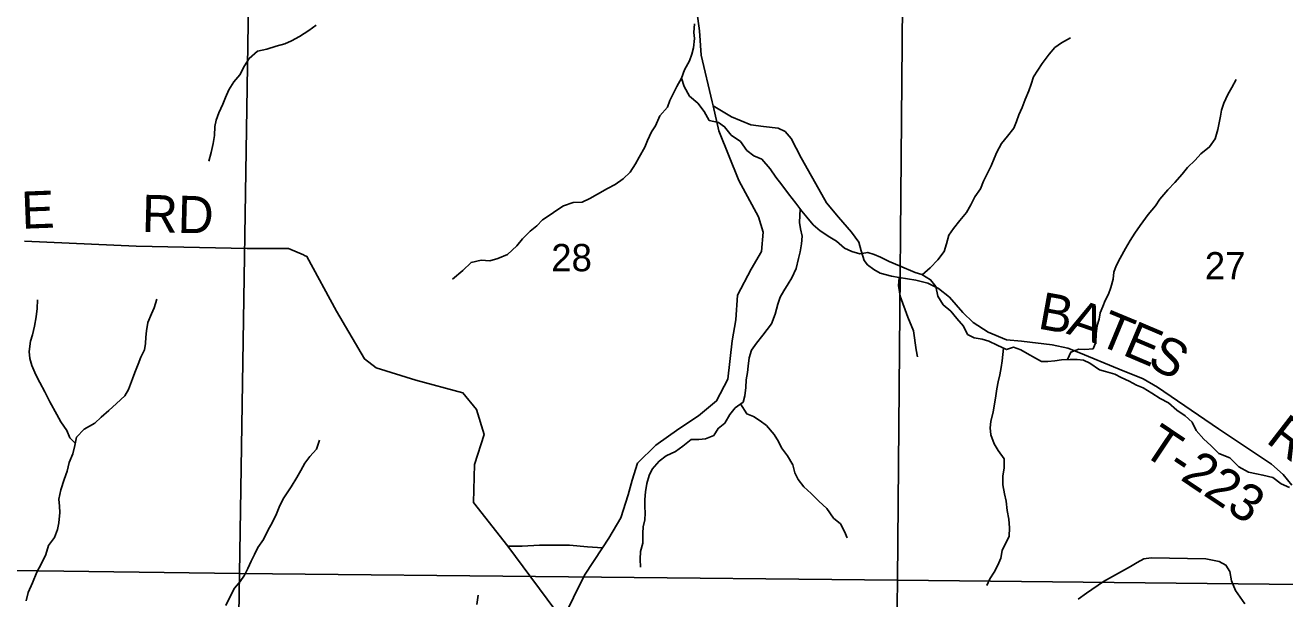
# Model space of a CAD drawing. Extents: x 2043100 to 2470832, y 443715 to 810583.
# Drawn here: x 2268319 to 2278495, y 675442 to 680076 of the extents above; entities that cross this region are included whole.
import ezdxf

# ---------------------------------------------------------------- set-up
doc = ezdxf.new("R2010")
doc.units = 0
for name, color, linetype in [('GM_X_County_Road', 7, 'Continuous'), ('GM_X_County_Road_Text', 7, 'Continuous'), ('GM_X_Minor_River', 7, 'Continuous'), ('GM_X_Section', 7, 'Continuous'), ('GM_X_Section_Text', 7, 'Continuous'), ('GM_X_State_Route', 7, 'Continuous'), ('GM_X_Township_Road', 7, 'Continuous'), ('GM_X_Township_Road_Text', 7, 'Continuous')]:
    doc.layers.add(name, color=color, linetype=linetype)

msp = doc.modelspace()

# ---------------------------------------------------------------- linework, layer by layer
at = {"layer": 'GM_X_County_Road'}
for points in [[(2268313, 678330), (2269216, 678290), (2270112, 678271), (2270447, 678271), (2270567, 678220)], [(2270567, 678220), (2270577, 678216), (2270595, 678208), (2270833, 677765), (2271060, 677380), (2271155, 677307), (2271474, 677209), (2271855, 677107), (2271966, 676970), (2272026, 676770), (2271949, 676527), (2271942, 676220), (2272218, 675867), (2272660, 675271)], [(2276826, 675440), (2276893, 675488), (2277031, 675582), (2277249, 675703), (2277302, 675734), (2277357, 675764), (2277415, 675773), (2277856, 675765), (2277966, 675744), (2278020, 675714), (2278051, 675662), (2278065, 675587), (2278097, 675510), (2278173, 675401)]]:
    msp.add_lwpolyline(points, dxfattribs=at)
at = {"layer": 'GM_X_Minor_River'}
for points in [[(2270671, 680077), (2270611, 680034), (2270534, 679984), (2270470, 679949), (2270418, 679926), (2270347, 679906), (2270271, 679883), (2270197, 679866), (2270130, 679807), (2270092, 679749), (2270053, 679674), (2270006, 679618), (2269964, 679555), (2269937, 679493), (2269915, 679437), (2269884, 679368), (2269861, 679308), (2269851, 679258), (2269848, 679186), (2269839, 679121), (2269823, 679049), (2269802, 678977)], [(2273726, 680086), (2273722, 680018), (2273727, 679968), (2273718, 679894), (2273706, 679842), (2273685, 679788), (2273645, 679715), (2273622, 679647)], [(2275566, 678058), (2275629, 678117), (2275692, 678180), (2275742, 678247), (2275761, 678311), (2275780, 678379), (2275820, 678434), (2275871, 678498), (2275924, 678563), (2275958, 678625), (2275991, 678690), (2276036, 678754), (2276062, 678817), (2276097, 678885), (2276123, 678941), (2276146, 679000), (2276169, 679050), (2276207, 679120), (2276256, 679179), (2276305, 679244), (2276327, 679298), (2276346, 679352), (2276374, 679410), (2276397, 679475), (2276428, 679545), (2276446, 679599), (2276465, 679658), (2276499, 679712), (2276534, 679768), (2276591, 679843), (2276637, 679896), (2276692, 679934), (2276764, 679973)], [(2273622, 679647), (2273583, 679582), (2273557, 679528), (2273526, 679468), (2273507, 679415), (2273447, 679343), (2273410, 679264), (2273379, 679214), (2273347, 679145), (2273324, 679091), (2273279, 679009), (2273249, 678956), (2273206, 678888), (2273149, 678835), (2273085, 678788), (2273023, 678756), (2272942, 678711), (2272882, 678676), (2272819, 678647), (2272747, 678643), (2272669, 678616), (2272615, 678583), (2272560, 678545), (2272498, 678504), (2272453, 678454), (2272399, 678411), (2272336, 678350), (2272292, 678294), (2272215, 678223), (2272137, 678192), (2272072, 678173), (2272004, 678179), (2271922, 678160), (2271855, 678093), (2271771, 678024)], [(2273622, 679647), (2273643, 679581), (2273686, 679503), (2273752, 679446), (2273805, 679380), (2273846, 679307), (2273920, 679291), (2273970, 679256), (2274023, 679188), (2274097, 679137), (2274150, 679065), (2274206, 679022), (2274269, 678993), (2274337, 678917), (2274384, 678848), (2274433, 678786), (2274485, 678714), (2274546, 678639), (2274593, 678575), (2274635, 678524), (2274686, 678462), (2274742, 678415), (2274821, 678364), (2274873, 678330), (2274938, 678275), (2274998, 678247), (2275062, 678228), (2275126, 678240), (2275178, 678223), (2275230, 678201), (2275299, 678168), (2275383, 678131), (2275510, 678078), (2275562, 678061), (2275634, 678019), (2275675, 677964), (2275693, 677888), (2275736, 677818), (2275797, 677767), (2275847, 677707), (2275900, 677644), (2275933, 677578), (2275987, 677550), (2276049, 677539), (2276103, 677522), (2276171, 677492), (2276248, 677455), (2276303, 677476), (2276364, 677454), (2276414, 677423), (2276480, 677385), (2276531, 677360), (2276581, 677358), (2276638, 677365), (2276692, 677373), (2276760, 677376), (2276818, 677375), (2276868, 677369), (2276921, 677346), (2276997, 677292), (2277047, 677277), (2277121, 677258), (2277174, 677230), (2277238, 677199), (2277296, 677169), (2277352, 677146), (2277421, 677102), (2277489, 677061), (2277556, 677024), (2277622, 676966), (2277689, 676921), (2277747, 676869), (2277780, 676802), (2277841, 676732), (2277897, 676681), (2277962, 676617), (2278052, 676582), (2278125, 676509), (2278203, 676466), (2278267, 676452), (2278319, 676441), (2278398, 676422), (2278466, 676370), (2278534, 676341)], [(2276739, 677375), (2276766, 677434), (2276831, 677459), (2276881, 677455), (2276947, 677462), (2276969, 677516), (2276970, 677582), (2276979, 677651), (2276995, 677701), (2277004, 677753), (2277024, 677803), (2277045, 677853), (2277071, 677904), (2277090, 677956), (2277108, 678024), (2277115, 678082), (2277134, 678133), (2277166, 678195), (2277207, 678272), (2277246, 678338), (2277284, 678396), (2277327, 678459), (2277392, 678548), (2277451, 678618), (2277485, 678671), (2277550, 678746), (2277607, 678806), (2277667, 678873), (2277710, 678927), (2277772, 678986), (2277817, 679037), (2277888, 679093), (2277932, 679158), (2277955, 679234), (2277964, 679288), (2277976, 679340), (2277985, 679391), (2278003, 679445), (2278034, 679517), (2278067, 679572), (2278103, 679638)], [(2274581, 678592), (2274574, 678483), (2274584, 678431), (2274597, 678373), (2274591, 678311), (2274580, 678245), (2274567, 678191), (2274548, 678110), (2274514, 678036), (2274483, 677986), (2274447, 677931), (2274418, 677879), (2274399, 677821), (2274379, 677742), (2274348, 677664), (2274279, 677573), (2274228, 677507), (2274188, 677450), (2274169, 677390), (2274160, 677320), (2274154, 677270), (2274145, 677211), (2274140, 677149), (2274134, 677081), (2274119, 677031), (2274055, 676984), (2274012, 676932), (2273971, 676861), (2273917, 676819), (2273882, 676760), (2273814, 676733), (2273762, 676729), (2273700, 676730), (2273633, 676674), (2273573, 676631), (2273497, 676598), (2273442, 676555), (2273385, 676489), (2273361, 676438), (2273342, 676372), (2273330, 676306), (2273325, 676244), (2273324, 676188), (2273328, 676134), (2273325, 676080), (2273313, 676024), (2273308, 675973), (2273309, 675891), (2273289, 675823), (2273288, 675763), (2273291, 675697)], [(2268327, 675425), (2268344, 675492), (2268377, 675572), (2268414, 675657), (2268450, 675727), (2268485, 675801), (2268508, 675872), (2268556, 675938), (2268581, 676001), (2268592, 676055), (2268599, 676139), (2268597, 676191), (2268592, 676247), (2268608, 676321), (2268633, 676406), (2268658, 676474), (2268675, 676544), (2268703, 676613), (2268720, 676681), (2268733, 676747), (2268797, 676812), (2268882, 676861), (2268933, 676909), (2268995, 676964), (2269056, 677021), (2269124, 677082), (2269153, 677134), (2269186, 677218), (2269204, 677269), (2269231, 677337), (2269254, 677395), (2269282, 677452), (2269291, 677504), (2269293, 677556), (2269298, 677606), (2269310, 677674), (2269341, 677743), (2269362, 677793), (2269384, 677863)], [(2268724, 676700), (2268681, 676743), (2268655, 676802), (2268608, 676872), (2268575, 676930), (2268518, 677033), (2268477, 677115), (2268437, 677189), (2268406, 677252), (2268373, 677328), (2268357, 677382), (2268352, 677440), (2268361, 677524), (2268379, 677574), (2268394, 677645), (2268407, 677719), (2268417, 677787), (2268418, 677857)], [(2276224, 677467), (2276213, 677364), (2276203, 677310), (2276192, 677252), (2276180, 677196), (2276169, 677138), (2276162, 677082), (2276150, 677015), (2276139, 676953), (2276120, 676873), (2276116, 676823), (2276121, 676767), (2276148, 676693), (2276180, 676641), (2276227, 676572), (2276229, 676496), (2276218, 676436), (2276217, 676363), (2276232, 676291), (2276244, 676230), (2276253, 676154), (2276266, 676084), (2276272, 676016), (2276269, 675949), (2276212, 675833), (2276201, 675771), (2276176, 675714), (2276146, 675656), (2276113, 675604), (2276089, 675549)], [(2274098, 677016), (2274148, 676935), (2274202, 676914), (2274258, 676880), (2274309, 676841), (2274371, 676769), (2274406, 676713), (2274428, 676662), (2274479, 676596), (2274522, 676524), (2274538, 676460), (2274565, 676405), (2274610, 676347), (2274670, 676292), (2274731, 676230), (2274795, 676171), (2274850, 676093), (2274905, 676048), (2274937, 675986), (2274960, 675934)], [(2269939, 675388), (2269978, 675465), (2270009, 675527), (2270055, 675582), (2270092, 675632), (2270118, 675686), (2270145, 675747), (2270172, 675801), (2270198, 675857), (2270245, 675922), (2270280, 675994), (2270316, 676061), (2270349, 676129), (2270376, 676196), (2270408, 676258), (2270469, 676347), (2270514, 676421), (2270545, 676478), (2270579, 676538), (2270618, 676591), (2270672, 676651), (2270697, 676724)], [(2271968, 675397), (2271979, 675471)]]:
    msp.add_lwpolyline(points, dxfattribs=at)
at = {"layer": 'GM_X_Section'}
for points in [[(2264848, 681021), (2270133, 680943), (2270050, 675647), (2264772, 675717)], [(2275412, 680867), (2275365, 675592), (2270050, 675647), (2270133, 680943)], [(2275412, 680867), (2280692, 680799), (2280621, 675536), (2275365, 675592)], [(2270050, 675647), (2269964, 670340), (2269548, 670345), (2264693, 670424), (2264772, 675717)], [(2270050, 675647), (2275365, 675592), (2275297, 670271), (2275177, 670269), (2269964, 670340)], [(2280621, 675536), (2280538, 670233), (2280338, 670236), (2275297, 670271), (2275365, 675592)]]:
    msp.add_lwpolyline(points, close=True, dxfattribs=at)
at = {"layer": 'GM_X_State_Route'}
msp.add_lwpolyline([(2272660, 675271), (2272838, 675633), (2272983, 675854), (2273034, 675931), (2273132, 676097), (2273191, 676281), (2273223, 676401), (2273267, 676538), (2273414, 676683), (2273600, 676814), (2273759, 676919), (2273905, 677040), (2273995, 677215), (2274031, 677525), (2274060, 677696), (2274075, 677894), (2274184, 678105), (2274268, 678248), (2274282, 678405), (2274244, 678529), (2274085, 678821), (2273923, 679223), (2273876, 679426), (2273869, 679457), (2273779, 679833), (2273768, 680031), (2273734, 680270)], dxfattribs=at)
at = {"layer": 'GM_X_Township_Road'}
for points in [[(2278552, 676359), (2278482, 676447), (2278389, 676530), (2277960, 676814), (2277467, 677151), (2277350, 677218), (2277156, 677297), (2276832, 677433), (2276742, 677466), (2276617, 677493), (2276369, 677524), (2276248, 677535), (2276100, 677596), (2275977, 677673), (2275894, 677755), (2275787, 677878), (2275697, 677950), (2275612, 677993), (2275514, 678017), (2275380, 678039), (2275317, 678049), (2275227, 678073), (2275175, 678102), (2275124, 678140), (2275096, 678174), (2275074, 678254), (2275055, 678324), (2274994, 678404), (2274891, 678525), (2274794, 678641), (2274754, 678707), (2274589, 679004), (2274506, 679160), (2274458, 679216), (2274401, 679243), (2274285, 679258), (2274181, 679272), (2274026, 679337), (2273876, 679426)], [(2275380, 678039), (2275374, 677972), (2275389, 677886), (2275450, 677716), (2275495, 677606), (2275516, 677452), (2275528, 677398)], [(2272983, 675854), (2272863, 675861), (2272717, 675876), (2272473, 675874), (2272333, 675867), (2272218, 675867)]]:
    msp.add_lwpolyline(points, dxfattribs=at)

# ---------------------------------------------------------------- texts
at = {"layer": 'GM_X_County_Road_Text'}
for s, rotation, p in [('E', 2.1904, (2268293, 678431)), ('RD', 358.5194, (2269259, 678407))]:
    msp.add_text(s, height=300, rotation=rotation, dxfattribs=at).set_placement(p)
at = {"layer": 'GM_X_Section_Text'}
for s, p in [('28', (2272569, 678088)), ('27', (2277849, 678022))]:
    msp.add_text(s, height=220.8, rotation=0, dxfattribs=at).set_placement(p)
at = {"layer": 'GM_X_Township_Road_Text'}
for s, rotation, p in [('B', 349.8023, (2276492, 677627)), ('A', 340.9487, (2276723, 677587)), ('T', 337.4959, (2276968, 677502)), ('E', 336.9657, (2277174, 677417)), ('S', 330.9417, (2277373, 677332)), ('R', 322.3167, (2278334, 676712)), ('T-223', 326.154, (2277328, 676620))]:
    msp.add_text(s, height=300, rotation=rotation, dxfattribs=at).set_placement(p)

doc.saveas('drawing.dxf')
